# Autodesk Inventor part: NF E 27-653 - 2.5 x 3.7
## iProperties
Created: 2004-01
Part Number: NF E 27-653 - 2.5 x 3.7
Vendor: Autodesk Inc.
Document SubType Name: Modeling
Designer: Administrator
Material: Default
Description: Woodruff Key
Standard: NF E 27-653
Size Designation: 2.5 x 3.7
Density: 1 g/cm^3
Control State: 0
Master: False
Checked Out: False
Shininess: 64.0
Length Units: 11269
Angle Units: 11279
Time Units: 11290
Mass Units: 11283
Length Display Precision: 3
Angle Display Precision: 2
Compacted: True
Density: 0.0
Volumn: 0.0
Area: 0.0
PropertySet Name: Model Information
Author: Administrator
Revision Number: 8
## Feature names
1. Body [Extrusion]
2. Chamfer1
